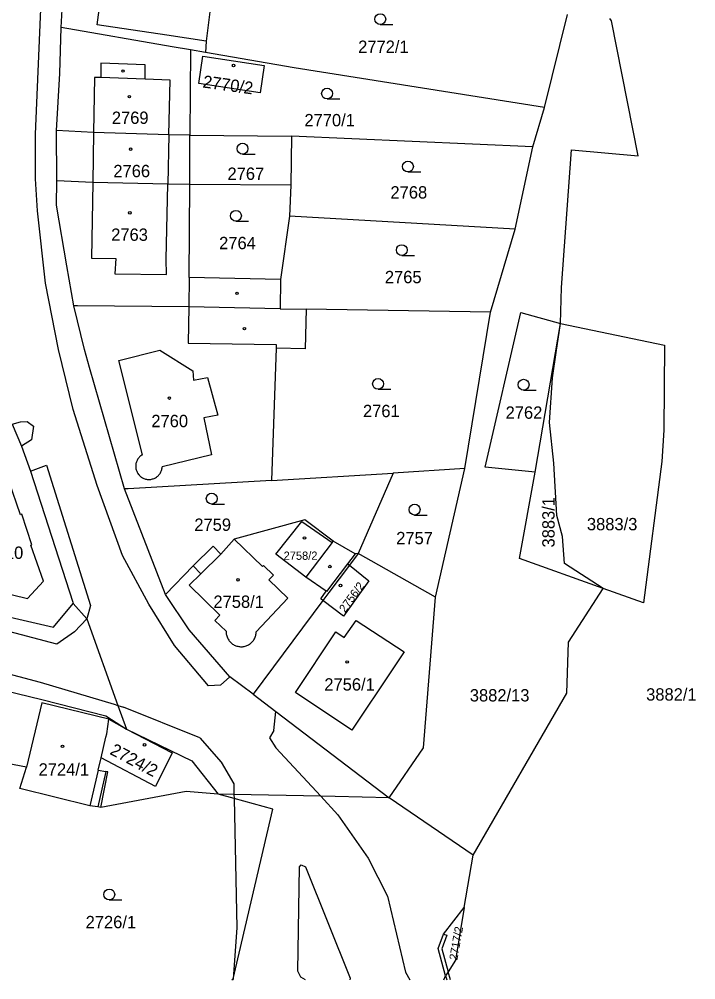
# Model space of a CAD drawing. Extents: x -527335 to -526256, y -1079142 to -1077836.
# Drawn here: x -526999.4 to -526906.2, y -1079141.5 to -1079009.2 of the extents above; entities that cross this region are included whole.
import ezdxf

# ---------------------------------------------------------------- set-up
doc = ezdxf.new("R2010")
doc.units = 0
for name, color, linetype in [('Hranice parcel', 7, 'Continuous'), ('Parcelní čísla', 7, 'Continuous'), ('Vnitřní kresba', 7, 'Continuous'), ('Značky budov', 7, 'Continuous'), ('Značky kultur', 7, 'Continuous')]:
    doc.layers.add(name, color=color, linetype=linetype)

msp = doc.modelspace()

# ---------------------------------------------------------------- linework, layer by layer
at = {"layer": 'Hranice parcel'}
for p, q in [((-526993.58, -1079010.29), (-526992.59, -1078994.21)), ((-526926.99, -1079021.34), (-526923.82, -1079008.49)), ((-526975.76, -1079013.38), (-526975.83, -1079025.14)), ((-526973.68, -1079013.74), (-526975.76, -1079013.38)), ((-526961.48, -1079015.86), (-526973.68, -1079013.74)), ((-526926.99, -1079021.34), (-526961.48, -1079015.86)), ((-526928.59, -1079026.75), (-526926.99, -1079021.34)), ((-526994.18, -1079031.41), (-526994.21, -1079024.51)), ((-526975.87, -1079031.93), (-526975.83, -1079025.14)), ((-526975.83, -1079025.14), (-526961.85, -1079025.27)), ((-526961.85, -1079025.27), (-526961.95, -1079032.04)), ((-526928.59, -1079026.75), (-526961.85, -1079025.27)), ((-526931.03, -1079038.09), (-526928.59, -1079026.75)), ((-526961.95, -1079032.04), (-526975.87, -1079031.93)), ((-526961.95, -1079032.04), (-526962.14, -1079036.28)), ((-526962.14, -1079036.28), (-526963.38, -1079045.02)), ((-526931.03, -1079038.09), (-526962.14, -1079036.28)), ((-526934.42, -1079049.52), (-526931.03, -1079038.09)), ((-526963.38, -1079045.02), (-526963.42, -1079049.05)), ((-526963.42, -1079049.05), (-526959.83, -1079049.11)), ((-526934.42, -1079049.52), (-526959.83, -1079049.11)), ((-526937.98, -1079071.07), (-526934.42, -1079049.52)), ((-526928.28, -1079071.58), (-526924.77, -1079051.08)), ((-526964.58, -1079072.72), (-526947.84, -1079071.72)), ((-526947.84, -1079071.72), (-526952.64, -1079082.8)), ((-526937.98, -1079071.07), (-526947.84, -1079071.72)), ((-526942, -1079088.79), (-526937.98, -1079071.07)), ((-526979.19, -1079088.45), (-526984.86, -1079073.9)), ((-526953.05, -1079082.84), (-526956.09, -1079081.1)), ((-526952.64, -1079082.8), (-526953.87, -1079084.41)), ((-526952.64, -1079082.8), (-526953.05, -1079082.84)), ((-526942, -1079088.79), (-526952.64, -1079082.8)), ((-526957.52, -1079089.25), (-526967.13, -1079102.16)), ((-526943.64, -1079109.56), (-526942, -1079088.79)), ((-526948.41, -1079116.44), (-526943.64, -1079109.56)), ((-526936.82, -1079124.34), (-526948.41, -1079116.44)), ((-526938.05, -1079131.59), (-526936.82, -1079124.34))]:
    msp.add_line(p, q, dxfattribs=at)
for points in [[(-526972.18, -1078997.1), (-526972.98, -1079000.63), (-526972.95, -1079007.03), (-526973.6, -1079012.17), (-526973.68, -1079013.74)], [(-526924.77, -1079051.08), (-526924.66, -1079046.13), (-526923.27, -1079027.14), (-526914.08, -1079027.98), (-526917.74, -1079009.39), (-526917.97, -1079009.06)], [(-526994.21, -1079024.51), (-526993.76, -1079016.63), (-526993.58, -1079010.29)], [(-526975.76, -1079013.38), (-526978.26, -1079012.95), (-526993.58, -1079010.29)], [(-526974.63, -1079018), (-526974.06, -1079014.26), (-526965.59, -1079015.55), (-526966.15, -1079019.3), (-526974.63, -1079018)], [(-526975.83, -1079025.14), (-526978.72, -1079025.11), (-526989.12, -1079024.77), (-526994.21, -1079024.51)], [(-526991.83, -1079048.67), (-526992.77, -1079043.16), (-526994.21, -1079034.79), (-526994.18, -1079031.41)], [(-526975.87, -1079031.93), (-526978.87, -1079031.91), (-526989.23, -1079031.65), (-526994.18, -1079031.41)], [(-526963.38, -1079045.02), (-526975.94, -1079044.75), (-526975.87, -1079031.93)], [(-526963.42, -1079049.05), (-526976, -1079048.8), (-526991.33, -1079048.67), (-526991.83, -1079048.67)], [(-526984.86, -1079073.9), (-526989.68, -1079057.15), (-526990.38, -1079054.69), (-526991.83, -1079048.67)], [(-526959.83, -1079049.11), (-526959.97, -1079054.59), (-526963.97, -1079054.51), (-526964.58, -1079072.72)], [(-526928.28, -1079071.58), (-526935.16, -1079070.89), (-526930.27, -1079049.59), (-526924.77, -1079051.08)], [(-526918.92, -1079087.59), (-526924.25, -1079084.15), (-526924.53, -1079080.46), (-526925.29, -1079077.55), (-526925.71, -1079070.34), (-526926.3, -1079064.74), (-526925.9, -1079058.59), (-526925.39, -1079055.11), (-526924.77, -1079051.08)], [(-526924.77, -1079051.08), (-526910.45, -1079054.06), (-526910.54, -1079065.78), (-526910.82, -1079070.11), (-526913.35, -1079089.58), (-526918.92, -1079087.59)], [(-527000.3, -1079064.95), (-526999.03, -1079067.99), (-526997.79, -1079071.43), (-526991.96, -1079089.49), (-526991.9, -1079089.68)], [(-526918.92, -1079087.59), (-526930.42, -1079083.47), (-526928.28, -1079071.58)], [(-526964.58, -1079072.72), (-526984.32, -1079073.9), (-526984.86, -1079073.9)], [(-526956.09, -1079081.1), (-526960.02, -1079078.17), (-526969.73, -1079080.81), (-526971.59, -1079082.86), (-526972.64, -1079081.8), (-526975.39, -1079084.5), (-526979.19, -1079088.45)], [(-526953.05, -1079082.84), (-526954.11, -1079084.23), (-526957, -1079088.03), (-526957.07, -1079087.98), (-526959.89, -1079086.05), (-526963.98, -1079082.86), (-526960.43, -1079078.38), (-526956.23, -1079081.29), (-526956.09, -1079081.1)], [(-526953.87, -1079084.41), (-526956.71, -1079088.16), (-526957.52, -1079089.25)], [(-526953.87, -1079084.41), (-526951.17, -1079086.54), (-526954.69, -1079091.43), (-526957.52, -1079089.25)], [(-526936.82, -1079124.34), (-526923.9, -1079102.05), (-526923.68, -1079095.01), (-526918.92, -1079087.59)], [(-526967.13, -1079102.16), (-526970.32, -1079099.79), (-526975.94, -1079093.33), (-526979.19, -1079088.45)], [(-527006.59, -1079090.18), (-526994.63, -1079092.92), (-526991.9, -1079089.68)], [(-526991.9, -1079089.68), (-526990.02, -1079091.79), (-526985.75, -1079103.72), (-526984.58, -1079106.98)], [(-527008.36, -1079099.95), (-526996.25, -1079102.89), (-526987.44, -1079105.14), (-526984.58, -1079106.98)], [(-526967.13, -1079102.16), (-526963.98, -1079104.57), (-526948.41, -1079116.44)], [(-526984.58, -1079106.98), (-526978.28, -1079110.24), (-526980.57, -1079114.9), (-526988.08, -1079110.95), (-526987.42, -1079108.12), (-526987.3, -1079107.62), (-526986.99, -1079105.64), (-526984.58, -1079106.98)], [(-526984.58, -1079106.98), (-526975.58, -1079111.34), (-526971.93, -1079115.94)], [(-526971.93, -1079115.94), (-526976.33, -1079115.57), (-526988.12, -1079117.78), (-526988.51, -1079117.72), (-526989.62, -1079117.54), (-526999.27, -1079115.18), (-526998.37, -1079112.24), (-527009.82, -1079110.06)], [(-526969.89, -1079141.41), (-526964.4, -1079118), (-526969.76, -1079116.53), (-526971.93, -1079115.94)], [(-526948.41, -1079116.44), (-526955.84, -1079116.28), (-526957.82, -1079116.24), (-526969.77, -1079115.99), (-526971.93, -1079115.94)], [(-526940.61, -1079141.01), (-526941.63, -1079137.22), (-526940.92, -1079135.23), (-526938.05, -1079131.59)], [(-526938.05, -1079131.59), (-526939.27, -1079138.83), (-526940.25, -1079140.42), (-526940.61, -1079141.01)], [(-526940.86, -1079141.53), (-526940.61, -1079141.01)], [(-526970.05, -1079141.53), (-526969.89, -1079141.41)]]:
    msp.add_lwpolyline(points, dxfattribs=at)
at = {"layer": 'Vnitřní kresba'}
for p, q in [((-526988.63, -1079009.95), (-526987.21, -1078999.98)), ((-526997.1, -1079025), (-526996.31, -1079006.69)), ((-526979.03, -1079011.37), (-526988.63, -1079009.95)), ((-526973.6, -1079012.17), (-526979.03, -1079011.37)), ((-526988.11, -1079015.21), (-526988.12, -1079017.21)), ((-526982.01, -1079015.44), (-526988.11, -1079015.21)), ((-526982.02, -1079017.44), (-526982.01, -1079015.44)), ((-526988.99, -1079017.18), (-526989.12, -1079024.77)), ((-526988.12, -1079017.21), (-526988.99, -1079017.18)), ((-526982.02, -1079017.44), (-526988.12, -1079017.21)), ((-526978.56, -1079017.57), (-526982.02, -1079017.44)), ((-526978.72, -1079025.11), (-526978.56, -1079017.57)), ((-526997.09, -1079031.14), (-526997.1, -1079025)), ((-526989.12, -1079024.77), (-526989.23, -1079031.65)), ((-526978.72, -1079025.11), (-526978.87, -1079031.91)), ((-526996.85, -1079035.58), (-526997.09, -1079031.14)), ((-526989.23, -1079031.65), (-526989.41, -1079042.08)), ((-526979.09, -1079042.22), (-526978.87, -1079031.91)), ((-526995.75, -1079045.53), (-526996.85, -1079035.58)), ((-526989.41, -1079042.08), (-526986.04, -1079042.13)), ((-526986.04, -1079042.13), (-526986.18, -1079044.27)), ((-526979.05, -1079044.35), (-526979.09, -1079042.22)), ((-526986.18, -1079044.27), (-526979.05, -1079044.35)), ((-526993.94, -1079054.67), (-526995.75, -1079045.53)), ((-526975.94, -1079044.75), (-526976, -1079048.8)), ((-526976, -1079048.8), (-526976.07, -1079053.8)), ((-526991.93, -1079062.93), (-526993.94, -1079054.67)), ((-526985.61, -1079056.17), (-526979.98, -1079054.79)), ((-526979.98, -1079054.79), (-526975.45, -1079057.6)), ((-526976.07, -1079053.8), (-526963.96, -1079054.01)), ((-526963.96, -1079054.01), (-526963.97, -1079054.51)), ((-526982.38, -1079069.18), (-526985.61, -1079056.17)), ((-526975.45, -1079057.6), (-526975.34, -1079058.88)), ((-526975.34, -1079058.88), (-526973.41, -1079058.52)), ((-526973.41, -1079058.52), (-526972.01, -1079063.72)), ((-526988.62, -1079073.43), (-526991.93, -1079062.93)), ((-526972.01, -1079063.72), (-526973.93, -1079064.11)), ((-526973.93, -1079064.11), (-526972.86, -1079069.19)), ((-527000.3, -1079064.95), (-526999.18, -1079064.63)), ((-526999.18, -1079064.63), (-526998.24, -1079064.6)), ((-526998.24, -1079064.6), (-526997.4, -1079065.25)), ((-526997.4, -1079065.25), (-526997.64, -1079067.14)), ((-526997.64, -1079067.14), (-526999.03, -1079067.99)), ((-526972.86, -1079069.19), (-526979.66, -1079070.86)), ((-526997.79, -1079071.43), (-526995.59, -1079070.62)), ((-526995.59, -1079070.62), (-526989.55, -1079089.95)), ((-526999.16, -1079077.44), (-527000.78, -1079072.77)), ((-526985.11, -1079083.05), (-526988.62, -1079073.43)), ((-526998.99, -1079077.38), (-526999.16, -1079077.44)), ((-526997.6, -1079081.58), (-526998.99, -1079077.38)), ((-526965.85, -1079084.59), (-526969.73, -1079080.81)), ((-526956.23, -1079081.29), (-526959.89, -1079086.05)), ((-526997.76, -1079081.63), (-526997.6, -1079081.58)), ((-526996.01, -1079086.61), (-526997.76, -1079081.63)), ((-526981.48, -1079089.76), (-526985.11, -1079083.05)), ((-526971.59, -1079082.86), (-526974.33, -1079085.57)), ((-526974.33, -1079085.57), (-526975.39, -1079084.5)), ((-526965.7, -1079084.43), (-526965.85, -1079084.59)), ((-526964.32, -1079085.78), (-526965.7, -1079084.43)), ((-526954.11, -1079084.23), (-526953.87, -1079084.41)), ((-526998.21, -1079088.98), (-526996.01, -1079086.61)), ((-526974.33, -1079085.57), (-526975.94, -1079087.16)), ((-526964.95, -1079086.43), (-526964.32, -1079085.78)), ((-526962.37, -1079088.96), (-526964.95, -1079086.43)), ((-527005.52, -1079087.25), (-526998.21, -1079088.98)), ((-526975.94, -1079087.16), (-526971.7, -1079091.28)), ((-526957.8, -1079089.04), (-526957.07, -1079087.98)), ((-526966.71, -1079093.57), (-526962.37, -1079088.96)), ((-526957.52, -1079089.25), (-526957.8, -1079089.04)), ((-526989.55, -1079089.95), (-526990.02, -1079091.79)), ((-526977.96, -1079095.46), (-526981.48, -1079089.76)), ((-526994.16, -1079095.3), (-527010.79, -1079090.93)), ((-526990.02, -1079091.79), (-526991.73, -1079093.6)), ((-526971.7, -1079091.28), (-526972.4, -1079092)), ((-526972.4, -1079092), (-526970.84, -1079093.51)), ((-526954.61, -1079094.38), (-526952.95, -1079092.04)), ((-526952.95, -1079092.04), (-526946.32, -1079096.34)), ((-526991.73, -1079093.6), (-526994.16, -1079095.3)), ((-526961.27, -1079101.93), (-526955.72, -1079093.58)), ((-526955.72, -1079093.58), (-526954.61, -1079094.38)), ((-526973.28, -1079101.02), (-526977.96, -1079095.46)), ((-526946.32, -1079096.34), (-526947.9, -1079098.7)), ((-527007.27, -1079097.63), (-526996.46, -1079100.53)), ((-526970.32, -1079099.79), (-526971.63, -1079100.94)), ((-526947.9, -1079098.7), (-526953.53, -1079107.13)), ((-526996.46, -1079100.53), (-526986.26, -1079103.57)), ((-526971.63, -1079100.94), (-526973.28, -1079101.02)), ((-526953.53, -1079107.13), (-526961.27, -1079101.93)), ((-526996.25, -1079103.37), (-526998.37, -1079112.24)), ((-526986.99, -1079105.64), (-526996.25, -1079103.37)), ((-526986.26, -1079103.57), (-526985.75, -1079103.72)), ((-526985.75, -1079103.72), (-526984.99, -1079103.95)), ((-526974.48, -1079108.2), (-526984.99, -1079103.95)), ((-526964.26, -1079107.2), (-526963.98, -1079104.57)), ((-526964.26, -1079107.2), (-526964.86, -1079108.17)), ((-526974.48, -1079108.2), (-526971.51, -1079111.54)), ((-526964.86, -1079108.17), (-526964.02, -1079109.55)), ((-526964.02, -1079109.55), (-526957.82, -1079116.24)), ((-526988.47, -1079112.63), (-526988.08, -1079110.95)), ((-526971.51, -1079111.54), (-526969.8, -1079114.52)), ((-526988.47, -1079112.63), (-526989.62, -1079117.54)), ((-526987.41, -1079112.83), (-526988.51, -1079117.72)), ((-526988.47, -1079112.63), (-526987.41, -1079112.83)), ((-526988.12, -1079117.78), (-526987.13, -1079112.88)), ((-526987.13, -1079112.88), (-526987.41, -1079112.83)), ((-526969.8, -1079114.52), (-526969.77, -1079115.99)), ((-526969.77, -1079115.99), (-526969.76, -1079116.53)), ((-526969.76, -1079116.53), (-526969.39, -1079134.36)), ((-526957.82, -1079116.24), (-526955.45, -1079118.79)), ((-526955.45, -1079118.79), (-526951.28, -1079124.76)), ((-526951.28, -1079124.76), (-526948.63, -1079130.01)), ((-526960.96, -1079140.36), (-526960.76, -1079125.95)), ((-526960.76, -1079125.95), (-526960.52, -1079125.68)), ((-526960.52, -1079125.68), (-526959.9, -1079125.99)), ((-526959.9, -1079125.99), (-526953.77, -1079141.32)), ((-526948.63, -1079130.01), (-526946.15, -1079140.47)), ((-526969.39, -1079134.36), (-526969.89, -1079141.41)), ((-526940.46, -1079135.38), (-526941.14, -1079137.26)), ((-526940.92, -1079135.23), (-526940.46, -1079135.38)), ((-526941.14, -1079137.26), (-526940.25, -1079140.42)), ((-526960.57, -1079141.16), (-526960.96, -1079140.36)), ((-526946.15, -1079140.47), (-526945.56, -1079141.53)), ((-526940.61, -1079141.01), (-526940.46, -1079141.53)), ((-526939.93, -1079141.53), (-526940.25, -1079140.42)), ((-526969.89, -1079141.41), (-526969.95, -1079141.53)), ((-526959.92, -1079141.53), (-526960.57, -1079141.16)), ((-526953.77, -1079141.32), (-526953.81, -1079141.53))]:
    msp.add_line(p, q, dxfattribs=at)
for points in [[(-526982.38, -1079069.18), (-526982.48, -1079069.24), (-526982.58, -1079069.31), (-526982.67, -1079069.39), (-526982.76, -1079069.47), (-526982.84, -1079069.56), (-526982.92, -1079069.65), (-526982.99, -1079069.75), (-526983.06, -1079069.85), (-526983.11, -1079069.95), (-526983.16, -1079070.06), (-526983.2, -1079070.17), (-526983.24, -1079070.29), (-526983.27, -1079070.4), (-526983.29, -1079070.52), (-526983.3, -1079070.64), (-526983.3, -1079070.76), (-526983.3, -1079070.88), (-526983.29, -1079071), (-526983.27, -1079071.12), (-526983.24, -1079071.24), (-526983.21, -1079071.35), (-526983.17, -1079071.46), (-526983.12, -1079071.57), (-526983.06, -1079071.68), (-526983, -1079071.78), (-526982.93, -1079071.88), (-526982.85, -1079071.97), (-526982.77, -1079072.06), (-526982.68, -1079072.14), (-526982.59, -1079072.22), (-526982.49, -1079072.28), (-526982.39, -1079072.35), (-526982.28, -1079072.4), (-526982.17, -1079072.45), (-526982.06, -1079072.5), (-526981.95, -1079072.53), (-526981.83, -1079072.56), (-526981.71, -1079072.57), (-526981.59, -1079072.59), (-526981.47, -1079072.59), (-526981.35, -1079072.58), (-526981.23, -1079072.57), (-526981.11, -1079072.55), (-526981, -1079072.52), (-526980.88, -1079072.49), (-526980.77, -1079072.45), (-526980.66, -1079072.4), (-526980.56, -1079072.34), (-526980.45, -1079072.27), (-526980.36, -1079072.2), (-526980.27, -1079072.12), (-526980.18, -1079072.04), (-526980.1, -1079071.95), (-526980.02, -1079071.86), (-526979.95, -1079071.76), (-526979.89, -1079071.66), (-526979.84, -1079071.55), (-526979.79, -1079071.44), (-526979.75, -1079071.33), (-526979.71, -1079071.22), (-526979.69, -1079071.1), (-526979.67, -1079070.98), (-526979.66, -1079070.86)], [(-526970.84, -1079093.51), (-526970.84, -1079093.64), (-526970.83, -1079093.77), (-526970.82, -1079093.89), (-526970.79, -1079094.02), (-526970.76, -1079094.14), (-526970.72, -1079094.27), (-526970.67, -1079094.39), (-526970.62, -1079094.5), (-526970.56, -1079094.61), (-526970.49, -1079094.72), (-526970.41, -1079094.83), (-526970.33, -1079094.93), (-526970.24, -1079095.02), (-526970.15, -1079095.11), (-526970.05, -1079095.19), (-526969.95, -1079095.27), (-526969.84, -1079095.34), (-526969.73, -1079095.4), (-526969.61, -1079095.46), (-526969.5, -1079095.5), (-526969.37, -1079095.54), (-526969.25, -1079095.58), (-526969.12, -1079095.6), (-526969, -1079095.62), (-526968.87, -1079095.63), (-526968.74, -1079095.63), (-526968.61, -1079095.63), (-526968.49, -1079095.61), (-526968.36, -1079095.59), (-526968.23, -1079095.56), (-526968.11, -1079095.52), (-526967.99, -1079095.48), (-526967.87, -1079095.43), (-526967.76, -1079095.37), (-526967.65, -1079095.3), (-526967.55, -1079095.23), (-526967.45, -1079095.15), (-526967.35, -1079095.06), (-526967.26, -1079094.97), (-526967.18, -1079094.87), (-526967.1, -1079094.77), (-526967.03, -1079094.67), (-526966.96, -1079094.55), (-526966.9, -1079094.44), (-526966.85, -1079094.32), (-526966.81, -1079094.2), (-526966.77, -1079094.08), (-526966.75, -1079093.95), (-526966.73, -1079093.83), (-526966.71, -1079093.7), (-526966.71, -1079093.57)]]:
    msp.add_lwpolyline(points, dxfattribs=at)
at = {"layer": 'Značky budov'}
for centre in [(-526985.05, -1079016.3), (-526969.82, -1079015.54), (-526984.18, -1079019.84), (-526984, -1079027.06), (-526984.12, -1079035.85), (-526969.35, -1079046.94), (-526968.33, -1079051.81), (-526978.67, -1079061.37), (-526960.06, -1079080.65), (-526956.55, -1079084.59), (-526969.21, -1079086.41), (-526955.09, -1079087.19), (-526954.18, -1079097.74), (-526993.38, -1079109.37), (-526982.08, -1079109.15)]:
    msp.add_circle(centre, 0.175, dxfattribs=at)
at = {"layer": 'Značky kultur'}
for p, q in [((-526949.62, -1079009.9), (-526947.87, -1079009.9)), ((-526956.95, -1079020.15), (-526955.2, -1079020.15)), ((-526968.59, -1079027.75), (-526966.84, -1079027.75)), ((-526945.8, -1079030.21), (-526944.05, -1079030.21)), ((-526969.5, -1079037), (-526967.75, -1079037)), ((-526946.65, -1079041.73), (-526944.9, -1079041.73)), ((-526949.92, -1079060.16), (-526948.17, -1079060.16)), ((-526929.87, -1079060.28), (-526928.12, -1079060.28)), ((-526972.83, -1079075.98), (-526971.08, -1079075.98)), ((-526944.89, -1079077.49), (-526943.14, -1079077.49)), ((-526986.95, -1079130.53), (-526985.2, -1079130.53))]:
    msp.add_line(p, q, dxfattribs=at)
for centre in [(-526949.62, -1079009.15), (-526956.95, -1079019.4), (-526968.59, -1079027), (-526945.8, -1079029.46), (-526969.5, -1079036.25), (-526946.65, -1079040.98), (-526949.92, -1079059.41), (-526929.87, -1079059.53), (-526972.83, -1079075.23), (-526944.89, -1079076.74), (-526986.95, -1079129.78)]:
    msp.add_circle(centre, 0.75, dxfattribs=at)

# ---------------------------------------------------------------- texts
at = {"layer": 'Parcelní čísla'}
for s, height, p in [('2772/1', 1.7, (-526952.66, -1079013.8)), ('2769', 1.7, (-526986.59, -1079023.59)), ('2770/1', 1.7, (-526960.06, -1079023.92)), ('2766', 1.7, (-526986.38, -1079030.93)), ('2767', 1.7, (-526970.66, -1079031.3)), ('2768', 1.7, (-526948.21, -1079033.87)), ('2763', 1.7, (-526986.68, -1079039.7)), ('2764', 1.7, (-526971.81, -1079040.85)), ('2765', 1.7, (-526948.98, -1079045.54)), ('2761', 1.7, (-526952, -1079064)), ('2762', 1.7, (-526932.35, -1079064.22)), ('2760', 1.7, (-526981.15, -1079065.38)), ('2759', 1.7, (-526975.23, -1079079.67)), ('3883/3', 1.7, (-526921.15, -1079079.59)), ('2757', 1.7, (-526947.42, -1079081.51)), ('2810', 1.7, (-527003.85, -1079083.53)), ('2758/2', 1.14, (-526962.93, -1079083.66)), ('2758/1', 1.7, (-526972.6, -1079090.28)), ('2756/1', 1.7, (-526957.32, -1079101.68)), ('3882/1', 1.7, (-526912.99, -1079103.06)), ('3882/13', 1.7, (-526937.28, -1079103.18)), ('2724/1', 1.7, (-526996.68, -1079113.4)), ('2726/1', 1.7, (-526990.2, -1079134.43))]:
    msp.add_text(s, height=height, dxfattribs=at).set_placement(p)
for s, height, rotation, p in [('2770/2', 1.7, 352, (-526974.14, -1079018.56)), ('3883/1', 1.7, 90, (-526925.6, -1079081.96)), ('2756/2', 1.14, 54, (-526954.46, -1079091.02)), ('2724/2', 1.7, 332, (-526986.98, -1079110.38)), ('2717/2', 1.14, 80, (-526939.01, -1079138.9))]:
    msp.add_text(s, height=height, rotation=rotation, dxfattribs=at).set_placement(p)

doc.saveas('drawing.dxf')
